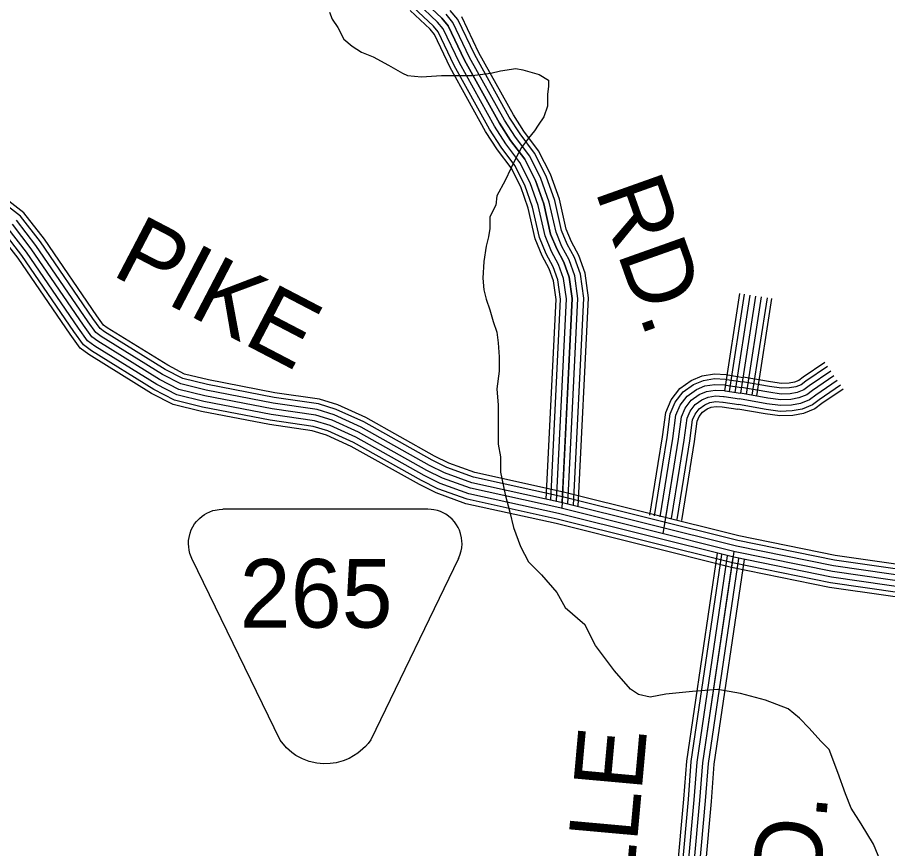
# Model space of a CAD drawing. Extents: x 1788175 to 1969470, y 584502 to 738744.
# Drawn here: x 1842071 to 1846760, y 654272 to 658752 of the extents above; entities that cross this region are included whole.
import ezdxf

# ---------------------------------------------------------------- set-up
doc = ezdxf.new("R2010")
doc.units = 0
for name, color, linetype in [('DESIGN - ROW - Easement Linework and Patterning', 7, 'Continuous'), ('DESIGN - ROW - Right-of-Way and Easement Labels', 7, 'Continuous'), ('DESIGN - TRANSPORTATION - Text', 7, 'Continuous'), ('SURVEY - CONTOURS - Index with Text', 7, 'Continuous'), ('SURVEY - CONTROL with Text', 7, 'Continuous'), ('SURVEY - TRANSPORTATION - Roads', 7, 'Continuous')]:
    doc.layers.add(name, color=color, linetype=linetype)

msp = doc.modelspace()

# ---------------------------------------------------------------- linework, layer by layer
at = {"layer": 'DESIGN - ROW - Easement Linework and Patterning'}
for points in [[(1843486.3, 654855.3), (1843011.9, 655835.8), (1843001.3, 655862.8), (1842996.8, 655880.8), (1842994.3, 655898.7), (1842993.4, 655914.3), (1842994.1, 655932.1), (1842996.2, 655948.6), (1843002, 655971.8), (1843008.5, 655989.4), (1843016.4, 656005.5), (1843026.4, 656021.7), (1843036.7, 656035.2), (1843052.2, 656051.4), (1843066.4, 656063.4), (1843079.6, 656072.6), (1843092.3, 656079.9), (1843108.9, 656087.6), (1843124.5, 656093.1), (1843137.3, 656096.5), (1843158.9, 656100.1), (1843178.2, 656101.1)], [(1844448.9, 655835.8), (1844455.1, 655853.5), (1844463.1, 655876.6), (1844465.9, 655893.3), (1844467.3, 655913.7), (1844466.9, 655929), (1844464.8, 655946.9), (1844459.6, 655969.3), (1844453.1, 655987.5), (1844446.3, 656002), (1844437.6, 656016.9), (1844425.9, 656032.9), (1844413.3, 656046.8), (1844394.6, 656063.2), (1844379.8, 656073.5), (1844365.8, 656081.2), (1844351.6, 656087.7), (1844335.3, 656093.4), (1844315.6, 656098.1), (1844301.7, 656100.1), (1844282.6, 656101.1), (1843178.2, 656101.1)], [(1844448.9, 655835.8), (1843975.8, 654858.2), (1843960.6, 654837.9), (1843946.2, 654821.6), (1843932.9, 654808.5), (1843904.8, 654785.4), (1843882.7, 654770.8), (1843858.8, 654758), (1843825.9, 654744.6), (1843788.2, 654734.5), (1843756.6, 654730), (1843721.5, 654728.9), (1843684.2, 654732.3), (1843643.7, 654741.6), (1843607.9, 654755), (1843572.3, 654774), (1843550.3, 654789.1), (1843520.9, 654814.5), (1843486.3, 654855.3)]]:
    msp.add_lwpolyline(points, dxfattribs=at)
at = {"layer": 'DESIGN - TRANSPORTATION - Text'}
for points in [[(1843753.9, 658780.4), (1843766.6, 658742.4), (1843798.3, 658698), (1843830, 658634.5), (1843874.4, 658596.4), (1843925.2, 658564.7), (1843988.6, 658539.3), (1844071.1, 658494.9), (1844147.2, 658450.5), (1844172.6, 658437.8), (1844248.7, 658431.5), (1844356.6, 658437.8), (1844458.1, 658437.8), (1844521.5, 658437.8), (1844623, 658450.5), (1844673.8, 658463.2), (1844756.3, 658475.9), (1844794.3, 658469.6), (1844883.2, 658444.2), (1844933.9, 658412.5), (1844933.9, 658380.7), (1844927.6, 658336.3), (1844927.6, 658272.9), (1844908.5, 658215.8), (1844876.8, 658171.4), (1844857.8, 658139.7), (1844826.1, 658101.6), (1844788, 658050.8), (1844756.3, 657993.7), (1844730.9, 657936.6), (1844699.2, 657873.2), (1844654.8, 657790.7), (1844648.4, 657740), (1844616.7, 657676.5), (1844616.7, 657613.1), (1844610.4, 657568.7), (1844597.7, 657517.9), (1844585, 657435.4), (1844578.6, 657346.6), (1844585, 657283.2), (1844597.7, 657232.4), (1844616.7, 657175.3), (1844635.7, 657111.9), (1844654.8, 657054.8), (1844661.1, 656997.7), (1844667.5, 656921.6), (1844667.5, 656845.4), (1844654.8, 656750.3), (1844661.1, 656661.4), (1844661.1, 656598), (1844661.1, 656521.9), (1844661.1, 656452.1), (1844673.8, 656382.3), (1844673.8, 656299.8), (1844699.2, 656179.3), (1844724.5, 656084.1), (1844743.6, 656001.6), (1844781.6, 655900.1), (1844826.1, 655817.7), (1844895.8, 655747.9), (1844978.3, 655652.7), (1845022.7, 655570.2), (1845128.5, 655480.2)], [(1846744.4, 654152.1), (1846685, 654295.3), (1846617, 654404.6), (1846564.6, 654489.7), (1846534, 654566.3), (1846492.1, 654681.2), (1846446.3, 654806.1), (1846401.2, 654851), (1846338.5, 654920.1), (1846285.5, 654975.1), (1846224.5, 655024.3), (1846101.5, 655072.5), (1845968.2, 655106.9), (1845844.8, 655129.1), (1845708.7, 655117.5), (1845564.6, 655104.1), (1845480.4, 655087.5), (1845418.8, 655102.6), (1845375.3, 655131.4), (1845289.2, 655229.1), (1845185.7, 655367.1), (1845128.5, 655480.2)]]:
    msp.add_lwpolyline(points, dxfattribs=at)
at = {"layer": 'SURVEY - CONTOURS - Index with Text'}
for points in [[(1844246.3, 658853.1), (1844358.4, 658747.1), (1844391.7, 658706.5), (1844480.5, 658520.8), (1844668.7, 658181.3), (1844729.1, 658088.2), (1844805.3, 657986.8), (1844863.3, 657871.8), (1844907.2, 657746.9), (1844944.5, 657584.1), (1844977.1, 657503.5), (1845015.9, 657432.7), (1845044.5, 657352.2), (1845060.6, 657235.8), (1845004.8, 656105)], [(1845006.3, 656136.5), (1845060.6, 657235.8), (1845044.5, 657352.2), (1845015.9, 657432.7), (1844977.1, 657503.5), (1844944.5, 657584.1), (1844907.2, 657746.9), (1844863.3, 657871.8), (1844805.3, 657986.8), (1844729.1, 658088.2), (1844668.7, 658181.3), (1844480.5, 658520.8), (1844391.7, 658706.5), (1844358.4, 658747.1), (1844246.3, 658853.1)], [(1844944.9, 656150.2), (1844998.4, 657233.1), (1844984, 657337.4), (1844959.1, 657407.3), (1844921, 657476.8), (1844885.1, 657565.4), (1844847.6, 657729.6), (1844806.2, 657847.4), (1844752.4, 657954), (1844678.2, 658052.7), (1844615.5, 658149.4), (1844425.4, 658492.4), (1844339, 658673), (1844313, 658704.7), (1844204.5, 658807.3)], [(1844975.6, 656143.5), (1845029.5, 657234.4), (1845014.3, 657344.8), (1844987.5, 657420), (1844949.1, 657490.1), (1844914.8, 657574.8), (1844877.4, 657738.3), (1844834.8, 657859.6), (1844778.9, 657970.4), (1844703.7, 658070.4), (1844642.1, 658165.4), (1844453, 658506.6), (1844365.3, 658689.7), (1844335.7, 658725.9), (1844225.4, 658830.2)], [(1844920.5, 656155.6), (1844973.6, 657232), (1844959.8, 657331.5), (1844936.5, 657397.1), (1844898.6, 657466.2), (1844861.5, 657558), (1844823.8, 657722.8), (1844783.4, 657837.7), (1844731.4, 657940.9), (1844658, 658038.5), (1844594.3, 658136.7), (1844403.4, 658481.1), (1844318, 658659.6), (1844294.8, 658687.9), (1844187.8, 658789)], [(1845037, 656128.9), (1845091.7, 657237.2), (1845074.8, 657359.6), (1845044.3, 657445.5), (1845005.2, 657516.8), (1844974.1, 657593.4), (1844937.1, 657755.5), (1844891.9, 657883.9), (1844831.7, 658003.3), (1844754.5, 658106), (1844695.3, 658197.3), (1844508.1, 658535), (1844418, 658723.3), (1844381.1, 658768.3)], [(1845067.7, 656121.2), (1845122.8, 657238.5), (1845105.1, 657366.9), (1845072.6, 657458.2), (1845033.2, 657530.1), (1845003.8, 657602.8), (1844966.9, 657764.1), (1844920.5, 657896.1), (1844858.2, 658019.7), (1844779.9, 658123.8), (1844721.9, 658213.3), (1844535.6, 658549.3), (1844444.4, 658740), (1844403.9, 658789.5)], [(1845093.1, 656114.9), (1845148.6, 657239.7), (1845130.2, 657373.1), (1845096.2, 657468.7), (1845056.5, 657541.1), (1845028.4, 657610.5), (1844991.6, 657771.3), (1844944.2, 657906.2), (1844880.1, 658033.3), (1844801, 658138.5), (1844743.9, 658226.5), (1844558.5, 658561), (1844466.2, 658753.9)], [(1845652.9, 648078.7), (1845871.4, 649281.1), (1845902.8, 649461.5), (1845906, 649512.6), (1845904.5, 649548), (1845901, 649574), (1845885.3, 649626.4), (1845501.6, 650863.1), (1845399.6, 651211.5), (1845387.4, 651288.1), (1845379.4, 651388.7), (1845476.1, 652472.9), (1845662.5, 654538.6), (1845678, 654743), (1845843.8, 655863.5)], [(1845679.5, 648086.9), (1845895.7, 649276.8), (1845927.4, 649458.6), (1845930.8, 649512.4), (1845929.2, 649550.2), (1845925.2, 649579.3), (1845909, 649633.6), (1845525.2, 650870.2), (1845423.8, 651216.9), (1845411.9, 651291), (1845404.2, 651388.6), (1845500.7, 652470.7), (1845687.1, 654536.6), (1845702.6, 654740.3), (1845867.9, 655857.5)], [(1845711.6, 648090.5), (1845926.3, 649271.3), (1845958.3, 649454.9), (1845961.8, 649512.1), (1845960.1, 649553), (1845955.6, 649585.8), (1845938.6, 649642.6), (1845554.9, 650879.1), (1845454.1, 651223.7), (1845442.7, 651294.7), (1845435.3, 651388.4), (1845531.6, 652468), (1845718, 654534), (1845733.5, 654736.9), (1845898.1, 655849.9)], [(1845742.6, 648087.5), (1845956.8, 649265.9), (1845989.1, 649451.3), (1845992.9, 649511.8), (1845991, 649555.7), (1845986, 649592.4), (1845968.3, 649651.7), (1845584.6, 650888.1), (1845484.4, 651230.6), (1845473.5, 651298.4), (1845466.4, 651388.3), (1845562.5, 652465.2), (1845748.9, 654531.4), (1845764.3, 654733.4), (1845932.9, 655873.2)], [(1845742.6, 648087.5), (1845956.8, 649265.9), (1845989.1, 649451.3), (1845992.9, 649511.8), (1845991, 649555.7), (1845986, 649592.4), (1845968.3, 649651.7), (1845584.6, 650888.1), (1845484.4, 651230.6), (1845473.5, 651298.4), (1845466.4, 651388.3), (1845562.5, 652465.2), (1845748.9, 654531.4), (1845764.3, 654733.4), (1845928.4, 655842.4)], [(1845772.4, 648078), (1845987.3, 649260.5), (1846019.9, 649447.7), (1846023.9, 649511.5), (1846021.9, 649558.5), (1846016.4, 649598.9), (1845998, 649660.7), (1845614.3, 650897), (1845514.7, 651237.4), (1845504.3, 651302.1), (1845497.5, 651388.1), (1845593.4, 652462.4), (1845779.8, 654528.9), (1845795.1, 654730), (1845958.8, 655836)], [(1845801.2, 648063.2), (1846017.8, 649255), (1846050.8, 649444), (1846055, 649511.2), (1846052.8, 649561.2), (1846046.8, 649605.5), (1846027.6, 649669.7), (1845644, 650906), (1845545, 651244.2), (1845535.1, 651305.8), (1845528.6, 651388), (1845624.2, 652459.7), (1845810.7, 654526.3), (1845825.9, 654726.5), (1845989.2, 655829.8)]]:
    msp.add_lwpolyline(points, dxfattribs=at)
at = {"layer": 'SURVEY - CONTROL with Text'}
for points in [[(1848386.4, 655553.3), (1848311.3, 655570.1), (1848077.6, 655610.4), (1847408.8, 655717.9), (1846477.7, 655851.3), (1845958.4, 655957.3), (1845014, 656193.1), (1844536.6, 656298.3), (1844395.8, 656349.2), (1844319, 656387.4), (1843949.3, 656594.6), (1843798.3, 656662.8), (1843699, 656693.9), (1843458.9, 656728.6), (1843100.5, 656797.9), (1842971.7, 656829.3), (1842881, 656876.6), (1842554.4, 657078.9), (1842534.9, 657093.2), (1842498.7, 657143.8), (1842216.9, 657556.2), (1842106.7, 657699), (1841829.6, 657912.5)], [(1848379.2, 655528.6), (1848306.3, 655544.9), (1848073.4, 655585.1), (1847404.9, 655692.5), (1846473.3, 655826), (1845952.7, 655932.2), (1845008.1, 656168.1), (1844529.4, 656273.5), (1844385.6, 656325.5), (1844306.9, 656364.7), (1843937.7, 656571.6), (1843789.1, 656638.7), (1843693.3, 656668.8), (1843454.6, 656703.2), (1843095, 656772.8), (1842962.5, 656805.1), (1842868.2, 656854.3), (1842540, 657057.6), (1842516.4, 657074.9), (1842477.6, 657129), (1842196.1, 657541.1), (1842088.4, 657680.7), (1841813.9, 657892.2)], [(1848362, 655468.9), (1848294.3, 655484), (1848063.2, 655523.9), (1847395.6, 655631.2), (1846462.7, 655764.9), (1845939, 655871.7), (1844993.9, 656107.7), (1844512.1, 656213.8), (1844361.2, 656268.4), (1844278, 656309.8), (1843909.7, 656516.2), (1843767, 656580.6), (1843679.5, 656608.1), (1843444.3, 656642.1), (1843081.8, 656712.2), (1842940.5, 656746.6), (1842837.5, 656800.4), (1842505.3, 657006.1), (1842471.7, 657030.7), (1842426.8, 657093.5), (1842145.9, 657504.6), (1842044.2, 657636.5)], [(1848370.6, 655498.7), (1848300.3, 655514.4), (1848068.3, 655554.5), (1847400.3, 655661.8), (1846468, 655795.4), (1845945.9, 655901.9), (1845001, 656137.9), (1844520.8, 656243.7), (1844373.4, 656297), (1844292.4, 656337.3), (1843923.7, 656543.9), (1843778, 656609.7), (1843686.4, 656638.5), (1843449.5, 656672.7), (1843088.4, 656742.5), (1842951.5, 656775.8), (1842852.9, 656827.3), (1842522.6, 657031.8), (1842494, 657052.8), (1842452.2, 657111.3), (1842171, 657522.9), (1842066.3, 657658.6)], [(1848344.7, 655409.2), (1848282.2, 655423.2), (1848053, 655462.8), (1847386.3, 655569.9), (1846452.1, 655703.7), (1845925.3, 655811.2), (1844979.7, 656047.3), (1844494.8, 656154.2), (1844336.8, 656211.3), (1844249, 656255), (1843881.8, 656460.8), (1843744.8, 656522.6), (1843665.7, 656547.5), (1843434, 656580.9), (1843068.6, 656651.6), (1842918.5, 656688.1), (1842806.8, 656746.5), (1842470.6, 656954.7), (1842427.1, 656986.6), (1842376, 657058), (1842095.7, 657468.2), (1842000, 657592.3)], [(1848353.3, 655439.1), (1848288.3, 655453.6), (1848058.1, 655493.3), (1847390.9, 655600.5), (1846457.4, 655734.3), (1845932.2, 655841.5), (1844986.8, 656077.5), (1844503.5, 656184), (1844349, 656239.9), (1844263.5, 656282.4), (1843895.8, 656488.5), (1843755.9, 656551.6), (1843672.6, 656577.8), (1843439.1, 656611.5), (1843075.2, 656681.9), (1842929.5, 656717.4), (1842822.2, 656773.4), (1842487.9, 656980.4), (1842449.4, 657008.6), (1842401.4, 657075.8), (1842120.8, 657486.4), (1842022.1, 657614.4)], [(1848337.8, 655385.4), (1848277.4, 655398.9), (1848048.9, 655438.4), (1847382.6, 655545.4), (1846447.9, 655679.4), (1845919.8, 655787.1), (1844974.1, 656023.3), (1844488, 656130.4), (1844327, 656188.6), (1844237.4, 656233.2), (1843870.6, 656438.7), (1843736, 656499.5), (1843660.2, 656523.3), (1843429.9, 656556.6), (1843063.3, 656627.5), (1842909.8, 656664.8), (1842794.6, 656725), (1842456.7, 656934.2), (1842409.3, 656969), (1842355.7, 657043.8), (1842075.7, 657453.7), (1841982.4, 657574.6)]]:
    msp.add_lwpolyline(points, dxfattribs=at)
at = {"layer": 'SURVEY - TRANSPORTATION - Roads'}
for points in [[(1845962.6, 657262.9), (1845881.2, 656739.3)], [(1845988, 657259), (1845906.6, 656735.3)], [(1846018.6, 657254.2), (1845937.2, 656730.6)], [(1846049.2, 657249.4), (1845967.8, 656725.8)], [(1846049.2, 657249.4), (1845967.8, 656725.8)], [(1846079.9, 657244.7), (1845998.5, 656721.1)], [(1846110.5, 657239.9), (1846029.1, 656716.3)], [(1846134.9, 657236.1), (1846053.5, 656712.5)], [(1846421.7, 656892.2), (1846304.8, 656812.3), (1846281.4, 656794.6), (1846258, 656785.2), (1846229.4, 656779.8), (1846189.1, 656778.4), (1846128.5, 656786.9), (1845982.9, 656812.2)], [(1846453.7, 656845.3), (1846337.9, 656766.2), (1846309.5, 656744.7), (1846273.9, 656730.5), (1846235.7, 656723.3), (1846186.1, 656721.5), (1846119.7, 656730.8), (1845973.2, 656756.4)], [(1846436.2, 656870.9), (1846319.8, 656791.4), (1846294.2, 656772), (1846265.2, 656760.4), (1846232.3, 656754.2), (1846187.8, 656752.6), (1846124.5, 656761.5), (1845978.5, 656786.9)], [(1845524.8, 656346.6), (1845547.5, 656490.3), (1845565, 656622.2), (1845593.9, 656689.6), (1845640.9, 656751.2), (1845702.6, 656794.6), (1845760.7, 656819.2), (1845826.8, 656829.9), (1845889.8, 656826.2), (1845898.9, 656824.6), (1845981.4, 656811.5)], [(1845549.2, 656342.8), (1845572, 656486.8), (1845589, 656615.6), (1845615.4, 656677), (1845658.2, 656733.2), (1845714.7, 656772.9), (1845767.6, 656795.3), (1845828.1, 656805), (1845886.8, 656801.7), (1845894.7, 656800.2), (1845977.6, 656787.1)], [(1846488.7, 656794.1), (1846374.1, 656715.9), (1846340.3, 656690.3), (1846291.3, 656670.7), (1846242.6, 656661.5), (1846182.9, 656659.4), (1846110.1, 656669.6), (1845962.5, 656695.3)], [(1846471.2, 656819.7), (1846356, 656741), (1846324.9, 656717.5), (1846282.6, 656700.6), (1846239.2, 656692.4), (1846184.5, 656690.4), (1846114.9, 656700.2), (1845967.8, 656725.8)], [(1846471.2, 656819.7), (1846356, 656741), (1846324.9, 656717.5), (1846282.6, 656700.6), (1846239.2, 656692.4), (1846184.5, 656690.4), (1846114.9, 656700.2), (1845967.8, 656725.8)], [(1845579.9, 656338), (1845602.6, 656482.3), (1845619.2, 656607.3), (1845642.4, 656661.2), (1845680, 656710.6), (1845729.8, 656745.6), (1845776.3, 656765.3), (1845829.7, 656773.9), (1845883.1, 656770.8), (1845889.5, 656769.7), (1845972.7, 656756.4)], [(1845610.5, 656333.1), (1845633.3, 656477.9), (1845649.4, 656599), (1845669.3, 656645.5), (1845701.7, 656688), (1845745, 656718.4), (1845784.9, 656735.3), (1845831.3, 656742.7), (1845879.4, 656740), (1845884.2, 656739.1), (1845967.8, 656725.8)], [(1845610.5, 656333.1), (1845633.3, 656477.9), (1845649.4, 656599), (1845669.3, 656645.5), (1845701.7, 656688), (1845745, 656718.3), (1845784.9, 656735.3), (1845831.3, 656742.7), (1845879.4, 656740), (1845884.2, 656739.1), (1845967.8, 656725.8)], [(1846520.1, 656748.1), (1846406.7, 656670.6), (1846368, 656641.3), (1846307, 656616.9), (1846248.8, 656606), (1846180, 656603.5), (1846101.4, 656614.5), (1845953, 656640.4)], [(1846506.1, 656768.6), (1846392.2, 656690.7), (1846355.7, 656663), (1846300, 656640.8), (1846246.1, 656630.6), (1846181.3, 656628.3), (1846105.3, 656638.9), (1845957.2, 656664.7)], [(1845641.1, 656328.3), (1845664, 656473.4), (1845679.5, 656590.7), (1845696.3, 656629.7), (1845723.5, 656665.3), (1845760.1, 656691.1), (1845793.5, 656705.3), (1845832.9, 656711.6), (1845875.7, 656709.1), (1845879, 656708.5), (1845963, 656695.2)], [(1845671.7, 656323.5), (1845694.7, 656469), (1845709.7, 656582.4), (1845723.3, 656614), (1845745.2, 656642.7), (1845775.2, 656663.8), (1845802.2, 656675.3), (1845834.5, 656680.5), (1845872, 656678.3), (1845873.8, 656678), (1845958.1, 656664.6)], [(1845697.1, 656319.5), (1845720.1, 656465.3), (1845734.7, 656575.5), (1845745.7, 656600.9), (1845763.2, 656624), (1845787.8, 656641.2), (1845809.3, 656650.4), (1845835.8, 656654.6), (1845869, 656652.7), (1845869.4, 656652.6), (1845954.1, 656639.2)], [(1845479.2, 656069.1), (1845524.9, 656347.2)], [(1845503.6, 656065.1), (1845549.3, 656343.2)], [(1845534.2, 656060.1), (1845579.9, 656338.2)], [(1845550.6, 655968.7), (1845610.5, 656333.1)], [(1845564.8, 656055.1), (1845610.5, 656333.1)], [(1845595.4, 656050), (1845641.1, 656328.1)], [(1845626, 656045), (1845671.7, 656323.1)], [(1845651.4, 656040.8), (1845697, 656318.9)]]:
    msp.add_lwpolyline(points, dxfattribs=at)

# ---------------------------------------------------------------- texts
at = {"layer": 'DESIGN - ROW - Easement Linework and Patterning'}
msp.add_text('265', height=369.6, dxfattribs=at).set_placement((1843268.7, 655462.6))
at = {"layer": 'DESIGN - ROW - Right-of-Way and Easement Labels'}
for s, rotation, p in [('RD.', 289.5661, (1845182.3, 657818.7)), ('PIKE', 332.4352, (1842571.3, 657366.9)), ('GLADEVILLE', 84.844, (1845192.5, 651891.7)), ('RD.', 84.844, (1846364.6, 653710.2))]:
    msp.add_text(s, height=370, rotation=rotation, dxfattribs=at).set_placement(p)

doc.saveas('drawing.dxf')
